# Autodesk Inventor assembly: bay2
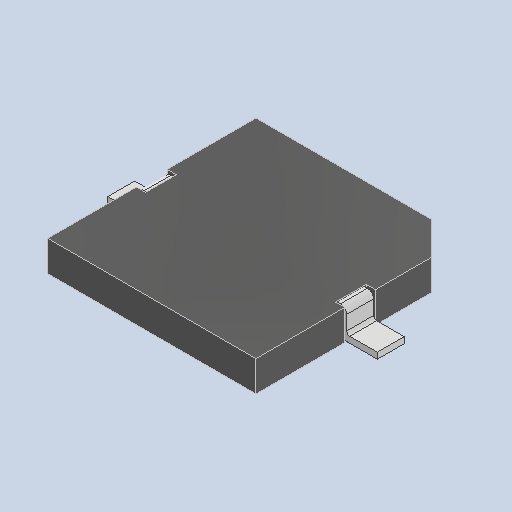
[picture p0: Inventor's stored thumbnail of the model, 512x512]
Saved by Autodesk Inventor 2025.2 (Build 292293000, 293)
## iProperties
Created: 2025-04
Part Number: bay2
Description: PART--DESC
Document SubType Name: Assembly
Designer: BennF
Author: BennF
Revision Number: NONE
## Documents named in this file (3)
- C:\Users\BennF\Nextcloud\Benutzer\CNC JarBeRi\existing parts\Electronics\RepRap A4988 Shied (USE WITHOUT ARDUINO)\reprap-a4988-1.snapshot.1\RepRap\RepRap\bay2.iam
- C:\Users\BennF\Nextcloud\Benutzer\CNC JarBeRi\existing parts\Electronics\RepRap A4988 Shied (USE WITHOUT ARDUINO)\reprap-a4988-1.snapshot.1\RepRap\RepRap\bay2 Geometry.ipt
- C:\Users\BennF\Nextcloud\Benutzer\CNC JarBeRi\existing parts\Electronics\RepRap A4988 Shied (USE WITHOUT ARDUINO)\reprap-a4988-1.snapshot.1\RepRap\RepRap\pin15.ipt
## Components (2 placed, 2 different names)
1. bay2 Geometry
2. pin15
